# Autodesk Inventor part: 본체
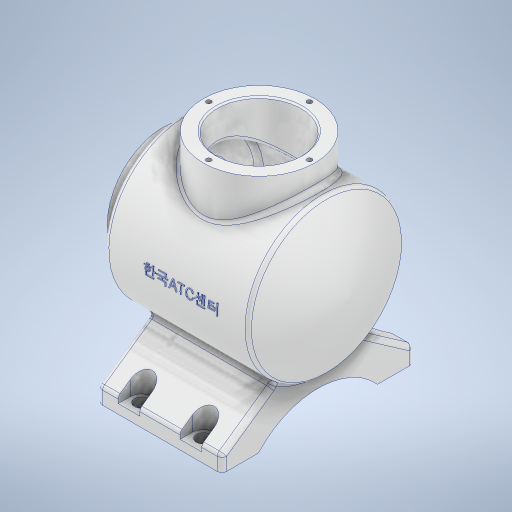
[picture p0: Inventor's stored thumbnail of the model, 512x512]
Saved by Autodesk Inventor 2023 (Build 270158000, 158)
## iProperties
Created: 2023-12
Part Number: 본체
Material: 알루미늄 6061
Document SubType Name: Modeling
Designer: asung
Density: 2.7 g/cm^3
Appearance: 알루미늄 - 평지
Author: asung
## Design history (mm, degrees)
sketch "스케치1"
  geometry: L1 (0, 0)-(120, 0); L2 (0, 0)-(0, -36); L3 (0, -36)-(12, -36); L4 (12, -36)-(12, -50); L5 (12, -50)-(104.642, -50); A1 r 113 centre (7.235, 7.279) between (104.642, -50) and (120, 0)
  constraints: 10 end point, 3 perpendicular, 2 point on circle, 1 centre point, 1 horizontal, 1 vertical
  dimensions: "d0" = 120 distance of L1.end L1.start; "d1" = 113 radius of A1; "d2" = 72 diameter of L3 L1; "d3" = 100 diameter of L5 L1; "d5" = 108 distance from line of L1.end L4; "d6" = 14.5578 diameter of A1.centre L1
revolve "회전1" sketch "스케치1" stored, may be unused: angle "d7" = 90 deg
sketch "스케치2"
  geometry: L1 (0, 36)-(0, -36) reference; L2 (0, -36)-(-12, -36) reference; L3 (-12, -36)-(-12, -50) reference; L4 (-12, -50)-(-104.642, -50) reference; L5 (-104.642, 50)-(-12, 50) reference; L6 (-12, 50)-(-12, 36) reference; L7 (-12, 36)-(0, 36) reference; L8 (0, 0)-(-120, 0); L9 (0, 0)-(0, 27); L10 (0, 27)-(-19, 27); L11 (-19, 27)-(-19, 40); L12 (-22, 43)-(-98.743, 43); A1 r 113 centre (-7.235, 7.279) between (-120, 0) and (-104.642, -50) reference; A2 r 113 centre (-7.235, -7.279) between (-104.642, 50) and (-120, 0) reference; A3 r 106 centre (-7.235, -7.279) between (-101.408, 41.377) and (-112.984, 0); A4 r 3 centre (-22, 40) between (-19, 40) and (-22, 43); A5 r 3 centre (-98.743, 40) between (-98.743, 43) and (-101.408, 41.377); 2 further points
  constraints: 10 end point, 8 point on circle, 4 tangent, 3 centre point, 3 point on line, 1 equal radius, 1 horizontal, 1 midpoint, 1 parallel, 1 perpendicular
  dimensions: "d8" = 7 radial gap between concentric circles of A2 A3; "d9" = 54 diameter of L10 L8; "d10" = 19 distance of L10.end L9.end; "d11" = 7 distance between parallel lines of L5 L12; "d12" = 7 distance from line of point (-12, 43) L11 (derived); "d13" = 3 radius of A4
revolve "회전2" sketch "스케치2" stored, may be unused: angle "d14" = 90 deg
node "작업 평면1"
sketch "스케치3"
  geometry: L1 (-104.642, 50)-(-104.642, -50) reference; L2 (-12, 50)-(-12, -50) reference; L3 (0, 0)-(-62, 0); C1 r 36 at (-62, 0)
  constraints: 2 end point, 1 centre point, 1 coincident, 1 horizontal
  dimensions: "d18" = 62 distance of L3.start L3.end; "d19" = 72 diameter of C1
extrude "돌출1" join sketch "스케치3" stored distance "d20" = 10; taper "d21" = 0 deg
sketch "스케치4"
  geometry: C1 r 36 at (0, 0) reference; C2 r 27 at (0, 0); 1 further point
  constraints: 1 centre point, 1 coincident
  dimensions: "d22" = 54 diameter of C2
extrude "돌출2" cut sketch "스케치4" stored distance "d23" = 10; taper "d24" = 0 deg
chamfer "모따기1" distance "d25" = 1; stored, may be unused: second distance "d26" = 2, angle "d27" = 45 deg
fillet "모깎기1" dims "d28" = 3
fillet "모깎기2" dims "d29" = 3
sketch "스케치5" dims "d30" = 65
  geometry: C1 r 36 at (0, 0) reference; C2 r 28 at (0, 0) reference; 3 further points
  constraints: 1 coincident, 1 vertical alignment, 2 other
hole "구멍1" sketch "스케치5" at (0, 32.5) diameter "d31" = 3.242; stored, may be unused: countersink angle "d35" = 90 deg, drill point angle "d37" = 118 deg; dims "d32" = 8, "d33" = 4, "d34" = 2, "d36" = 10
sketch "스케치6" dims "d41" = 65
  geometry: C1 r 36 at (0, 0) reference; C2 r 28 at (0, 0) reference; 3 further points
  constraints: 1 coincident, 1 vertical alignment, 2 other
hole "구멍2" sketch "스케치6" at (0, 32.5) diameter "d42" = 3.242; stored, may be unused: countersink angle "d46" = 90 deg, drill point angle "d48" = 118 deg; dims "d43" = 8, "d44" = 4, "d45" = 2, "d47" = 10
node "작업 평면2"
sketch "스케치7"
  geometry: L1 (-62, -67)-(-62, -77); L2 (-62, -77)-(-38.5, -77); L3 (26.694, -42.278)-(62, -67); L4 (62, -67)-(62, -77); L5 (62, -77)-(38.5, -77); L6 (-62, -67)-(-26.694, -42.278); C1 r 42.236 at (0, 0) reference; A1 r 50 centre (0, 0) between (26.694, -42.278) and (-26.694, -42.278) reference; A2 r 52.096 centre (0, -112.096) between (38.5, -77) and (-38.5, -77); 5 further points
  constraints: 12 end point, 5 point on circle, 2 coincident, 2 midpoint, 2 perpendicular, 2 point on line, 1 centre point, 1 collinear, 1 vertical, 1 vertical alignment
  dimensions: "d56" = 10 distance of L3.end L4.end; "d57" = 10 distance of L1.start L1.end; "d60" = 17 vertical distance of L2.end point (0, -60); "d61" = 77 distance of L5.end L2.end; "d62" = 55 deg angle of L3 L4; "d63" = 55 deg angle of L6 L1; "d75" = 124 distance of point (-62, -72) point (62, -72); "d101" = 77 distance from line of L2 point (0, 0)
extrude "돌출3" join sketch "스케치7" distance "d64" = 80; taper "d65" = 0 deg
node "작업 평면3"
sketch "스케치10"
  geometry: L1 (100, -42.278)-(20, -42.278) reference; L2 (20, -42.278)-(20, -42.278) reference; L3 (20, -42.278)-(100, -42.278) reference; L4 (100, -42.278)-(100, -42.278) reference; L5 (15, 50)-(15, -50) reference; L6 (102.91, -50)-(102.91, 50) reference; L7 (0, -36)-(0, 36) reference; L8 (12, -47)-(12, 47) reference; L9 (9, -36)-(9, 36) reference; L10 (15, 50)-(102.91, 50) reference; A1 r 113 centre (7.235, -7.279) between (120, 0) and (105.52, 48.48) reference; A2 r 10.263 centre (7.235, -7.279) between (0, 0) and (0, 0) reference; A3 r 10.263 centre (7.235, -7.279) between (0, 0) and (0, 0) reference; A4 r 113 centre (7.235, 7.279) between (105.52, -48.48) and (120, 0) reference; 3 further points
  constraints: 1 vertical alignment, 1 other
  dimensions: "d74" = 62 distance from line of point (62, 1.607) L7 (derived)
feature "엠보싱1" sketch "스케치10" dims "d0" = 120, "d1" = 113, "d2" = 72, "d3" = 100, "d5" = 108, "d6" = 14.5578, "d8" = 7, "d9" = 54, "d10" = 19, "d11" = 7, "d12" = 7 (derived), "d13" = 3, "d76" = 0.5, "d77" = 0
sketch "스케치11" dims "d80" = 9, "d82" = 9
  geometry: L1 (80, 23.5)-(80, 0) reference; L2 (80, 0)-(0, 0) reference; L3 (0, 0)-(0, 23.5) reference; L4 (0, -100.5)-(0, -77) reference; L5 (0, -77)-(80, -77) reference; L6 (80, -77)-(80, -100.5) reference; L7 (80, 0)-(80, -77) reference; L8 (0, -77)-(0, 0) reference; L9 (40, 23.5)-(40, -100.5); L10 (80, -38.5)-(0, -38.5); L11 (55.5, 15.5)-(24.5, 15.5); L12 (24.5, -92.5)-(55.5, -92.5); L13 (60, 15.5)-(20, -92.5); L14 (20, 15.5)-(60, -92.5); L15 (20, 11)-(20, -38.5); L16 (20, -77)-(20, -88); L17 (0, 23.5)-(80, 23.5) reference; L18 (80, -100.5)-(0, -100.5) reference; A1 r 4.5 centre (20, 15.5) between (24.5, 15.5) and (20, 11); A2 r 4.5 centre (20, -92.5) between (20, -88) and (24.5, -92.5); 4 further points
  constraints: 16 end point, 5 midpoint, 4 coincident, 4 point on circle, 2 centre point, 2 horizontal alignment, 2 perpendicular, 2 point on line, 1 horizontal, 1 parallel, 4 other
  dimensions: "d79" = 108 distance of L13.end L14.start; "d81" = 9 diameter of A1; "d83" = 9 diameter of A2
extrude "돌출4" cut sketch "스케치11" distance "d84" = 30; taper "d85" = 0 deg
node "작업 평면4"
sketch "스케치12" dims "d90" = 14
  geometry: L1 (80, -6.483)-(0, -6.483) reference; L2 (0, -70.517)-(80, -70.517) reference; L3 (13, 15.5)-(13, 29.361); L4 (13, 29.361)-(27, 29.361); L5 (27, 29.361)-(27, 15.5); L6 (67, 15.5)-(53, 15.5); L7 (53, 15.5)-(53, 31.728); L8 (53, 31.728)-(67, 31.728); L9 (67, 31.728)-(67, 15.5); L10 (80, 23.5)-(80, -6.483) reference; L11 (0, -6.483)-(0, 23.5) reference; L12 (0, 23.5)-(80, 23.5) reference; L13 (80, -100.5)-(0, -100.5) reference; L14 (0, -100.5)-(0, -70.517) reference; L15 (80, -70.517)-(80, -100.5) reference; C1 r 4.5 at (20, -92.5) reference; C2 r 4.5 at (20, 15.5) reference; C3 r 4.5 at (60, -92.5) reference; C4 r 4.5 at (60, 15.5) reference; 5 further points
  constraints: 14 end point, 3 parallel, 2 coincident, 1 horizontal, 1 perpendicular, 6 other
extrude "돌출5" cut sketch "스케치12" distance "d91" = 30; taper "d92" = 0 deg
fillet "모깎기5" dims "d93" = 3
fillet "모깎기10" dims "d98" = 3
fillet "모깎기11" dims "d99" = 3
fillet "모깎기12" dims "d100" = 3
node "솔리드1"
pattern_circular "원형 패턴1" dims angle "d39" = 360 deg
pattern_circular "원형 패턴2" dims angle "d50" = 360 deg
mirror "미러1"
node "투영된 루프1"
node "투영된 루프2"
node "투영된 루프3"
node "투영된 루프4"
node "투영된 루프6"
node "절단 모서리 투영1"
node "절단 모서리 투영2"
node "절단 모서리 투영5"
node "절단 모서리 투영6"
feature "A9D066F2-1C7D-4E18-AEED-F7BC21143FA4" dims "d31" = 3.242, "d32" = 8, "d33" = 4, "d34" = 2, "d35" = 90 deg, "d36" = 10, "d37" = 118 deg
other parameters: "d15" = 65, "d86" = -6
